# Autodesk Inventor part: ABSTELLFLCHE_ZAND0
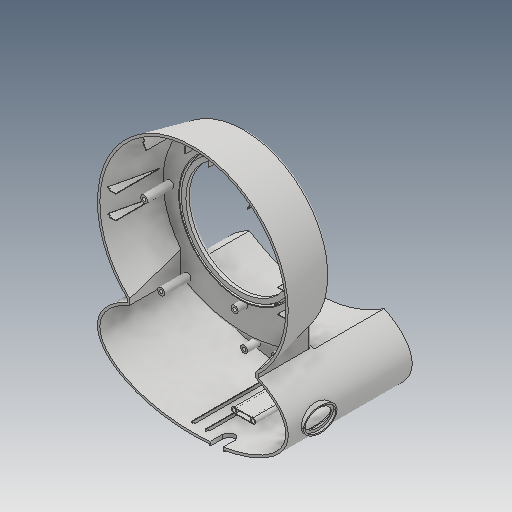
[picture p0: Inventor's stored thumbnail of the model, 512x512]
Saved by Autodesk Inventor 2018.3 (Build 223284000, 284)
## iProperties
Created: 2019-01
Part Number: ABSTELLFLCHE_ZAND0
Material: Polypropylene (PP)
Document SubType Name: Modeling
Designer: zand
Density: 0.902188 g/cm^3
Appearance: Vorgabe
Mass: 118.296 g
Surface Area: 1526.85 cm^2
Volume: 131.121 cm^3
Author: zand
Revision Number: 32LAST_VERSION
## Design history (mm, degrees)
feature "Basis1"
node "Volumenkörper1"
